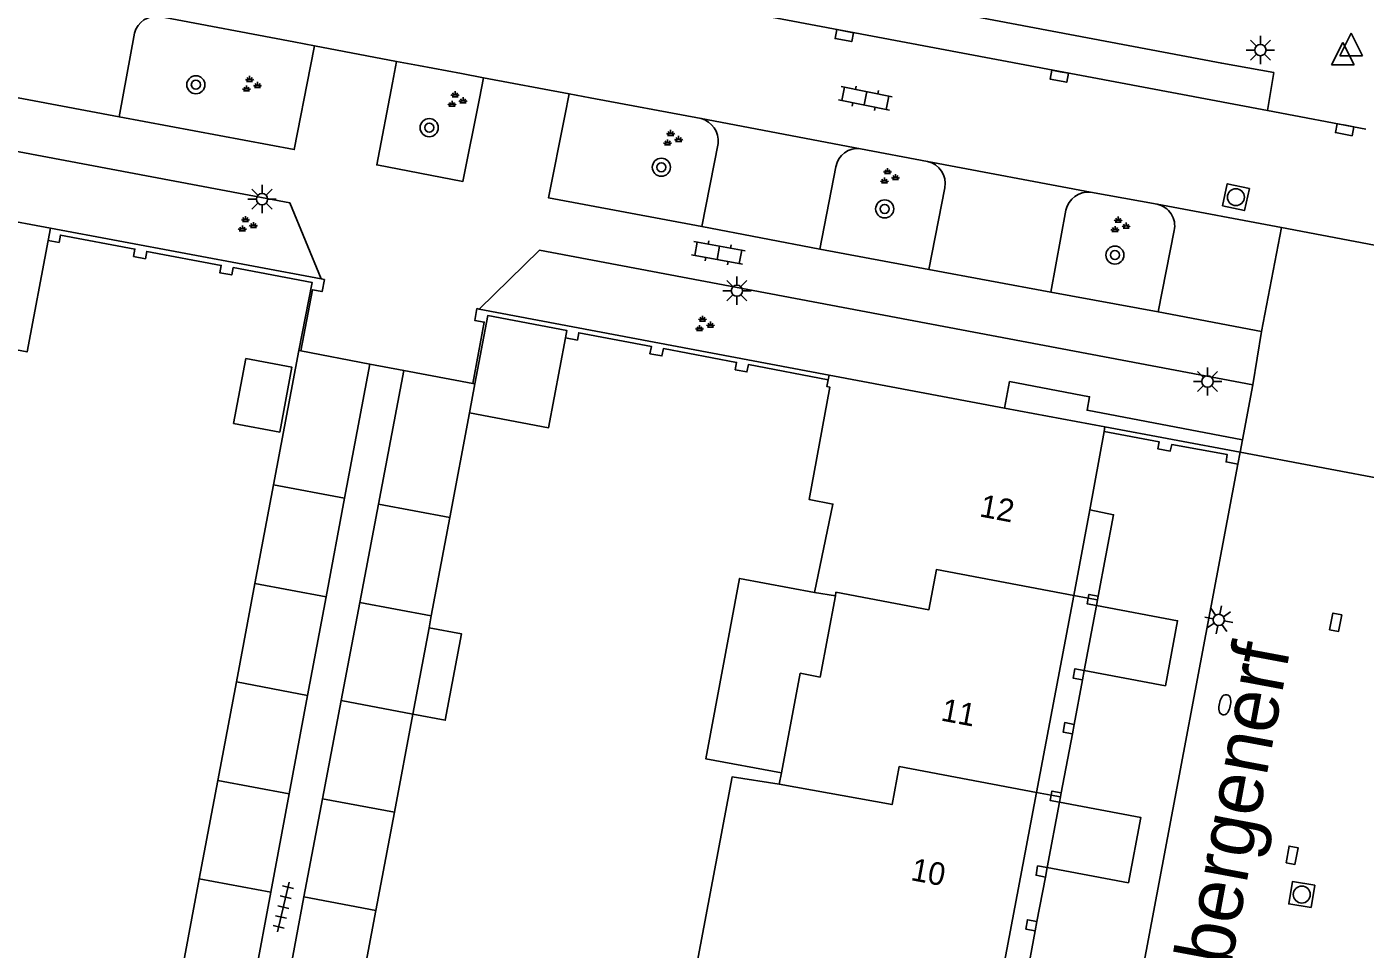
# Model space of a CAD drawing. Extents: x 124000 to 128010, y 398999 to 403000.
# Drawn here: x 126679.1 to 126738.3, y 399140 to 399180.7 of the extents above; entities that cross this region are included whole.
import ezdxf

# ---------------------------------------------------------------- set-up
doc = ezdxf.new("R2010")
doc.units = 0
for name, color, linetype in [('gg-afsc-muur', 7, 'Continuous'), ('gg-anno-huisnummerreeks BGT', 7, 'Continuous'), ('gg-anno-openbare ruimte label', 7, 'Continuous'), ('gg-bbg-bijgebouw', 7, 'Continuous'), ('gg-bbg-gedigitaliseerde bijgebouw', 7, 'Continuous'), ('gg-bbg-hoofdgebouw', 7, 'Continuous'), ('gg-bbg-luifel en loopbrug', 7, 'Continuous'), ('gg-bbg-onder overbouw', 7, 'Continuous'), ('gg-bbg-pand overbouw', 7, 'Continuous'), ('gg-bbg-pilaar onder overbouw', 7, 'Continuous'), ('gg-bbg-pilaar pand', 7, 'Continuous'), ('gg-bbg-tussenscheiding', 7, 'Continuous'), ('gg-bbg-tussenscheiding niveau 01', 7, 'Continuous'), ('gg-knt-verharding', 7, 'Continuous'), ('gg-knt-verharding nz', 7, 'Continuous'), ('gt-grn-groengrens', 7, 'Continuous'), ('gt-grn-weggrens', 7, 'Continuous'), ('gt-symb-boom', 7, 'Continuous'), ('gt-symb-brandkraan', 7, 'Continuous'), ('gt-symb-groenvak', 7, 'Continuous'), ('gt-symb-klinker verharding', 7, 'Continuous'), ('gt-symb-kolk', 7, 'Continuous'), ('gt-symb-kolk center center', 7, 'Continuous'), ('gt-symb-lichtmast', 7, 'Continuous'), ('gt-symb-rioolschacht', 7, 'Continuous'), ('gt-symb-tegel verharding', 7, 'Continuous'), ('gt-symb-waterafsluiter', 7, 'Continuous')]:
    doc.layers.add(name, color=color, linetype=linetype)

# ---------------------------------------------------------------- blocks, each defined once
blk = doc.blocks.new('gt0-LMAST')
at = {"layer": 'gt-symb-lichtmast'}
for p, q in [((-0.005, 0.246), (-0.005, 0.621)), ((-0.182, 0.173), (-0.447, 0.438)), ((0.172, 0.173), (0.437, 0.438)), ((-0.255, -0.004), (-0.63, -0.004)), ((-0.182, -0.181), (-0.447, -0.446)), ((-0.005, -0.254), (-0.005, -0.629)), ((0.437, -0.446), (0.172, -0.181)), ((0.245, -0.004), (0.62, -0.004))]:
    blk.add_line(p, q, dxfattribs=at)
blk.add_circle((-0.005, -0.004), 0.25, dxfattribs=at)
blk = doc.blocks.new('gt0-KOLK')
at = {"layer": 'gt-symb-kolk'}
blk.add_lwpolyline([(0, 0), (0.375, 0), (0.375, 0.4), (-0.375, 0.4), (-0.375, 0), (0, 0)], dxfattribs=at)
blk = doc.blocks.new('gt0-WAFSL')
at = {"layer": 'gt-symb-waterafsluiter'}
for p, q in [((-0.5, -0.333), (0, 0.667)), ((0, 0.667), (0.5, -0.333)), ((0.5, -0.333), (-0.5, -0.333))]:
    blk.add_line(p, q, dxfattribs=at)
blk = doc.blocks.new('gt0-BOOM')
at = {"layer": 'gt-symb-boom'}
for radius in [0.4, 0.2]:
    blk.add_circle((0, 0), radius, dxfattribs=at)
blk = doc.blocks.new('gt0-GRVAK')
at = {"layer": 'gt-symb-groenvak'}
for p, q in [((-0.11, 0.189), (-0.228, 0.24)), ((-0.182, 0.153), (0.088, 0.153)), ((-0.091, 0.211), (-0.156, 0.322)), ((-0.047, 0.214), (-0.047, 0.393)), ((-0.004, 0.211), (0.061, 0.322)), ((0.015, 0.189), (0.133, 0.24)), ((0.262, -0.052), (0.197, 0.059)), ((0.305, -0.049), (0.305, 0.13)), ((0.349, -0.052), (0.414, 0.059)), ((-0.245, -0.228), (-0.363, -0.177)), ((-0.318, -0.264), (-0.047, -0.264)), ((-0.226, -0.206), (-0.291, -0.095)), ((-0.183, -0.203), (-0.183, -0.024)), ((-0.139, -0.206), (-0.074, -0.095)), ((-0.12, -0.228), (-0.002, -0.177)), ((0.243, -0.074), (0.125, -0.023)), ((0.17, -0.11), (0.441, -0.11)), ((0.368, -0.074), (0.486, -0.023))]:
    blk.add_line(p, q, dxfattribs=at)
blk = doc.blocks.new('gt0-RS')
at = {"layer": 'gt-symb-rioolschacht'}
blk.add_lwpolyline([(-0.5, -0.5), (0.5, -0.5), (0.5, 0.5), (-0.5, 0.5)], close=True, dxfattribs=at)
blk.add_circle((0, 0), 0.375, dxfattribs=at)
blk = doc.blocks.new('gt0-KL1')
at = {"layer": 'gt-symb-klinker verharding'}
for p, q in [((-1.15, 0.3), (1.15, 0.3)), ((-1, -0.3), (-1, 0.3)), ((-0.5, 0.3), (-0.5, 0.45)), ((0, -0.3), (0, 0.3)), ((0.5, 0.3), (0.5, 0.45)), ((1, -0.3), (1, 0.3)), ((-1.15, -0.3), (1.15, -0.3)), ((-0.5, -0.45), (-0.5, -0.3)), ((0.5, -0.45), (0.5, -0.3))]:
    blk.add_line(p, q, dxfattribs=at)
blk = doc.blocks.new('gt0-BR')
at = {"layer": 'gt-symb-brandkraan'}
for centre, radius, start, end in [((-0.244, 0), 0.206, 107.56694, 252.43307), ((0.599, -2.664), 3, 106.89205, 107.56694), ((0, -0.691), 0.938, 73.10799, 106.89205), ((-0.599, -2.664), 3, 72.43309, 73.10799), ((0.244, 0), 0.206, 287.56695, 72.43309), ((0.599, 2.664), 3, 252.43307, 253.10797), ((0, 0.691), 0.938, 253.10797, 286.89206), ((-0.599, 2.664), 3, 286.89206, 287.56695)]:
    blk.add_arc(centre, radius, start, end, dxfattribs=at)
blk = doc.blocks.new('gt0-KOLKCC')
at = {"layer": 'gt-symb-kolk center center'}
blk.add_lwpolyline([(-0.375, 0.2), (0.375, 0.2), (0.375, -0.2), (-0.375, -0.2)], close=True, dxfattribs=at)
blk = doc.blocks.new('gt0-TEG1')
at = {"layer": 'gt-symb-tegel verharding'}
for p, q in [((-1.125, 0), (1.125, 0)), ((-0.9, -0.25), (-0.9, 0.25)), ((-0.45, -0.25), (-0.45, 0.25)), ((0, -0.25), (0, 0.25)), ((0.45, -0.25), (0.45, 0.25)), ((0.9, -0.25), (0.9, 0.25))]:
    blk.add_line(p, q, dxfattribs=at)

msp = doc.modelspace()

# ---------------------------------------------------------------- linework, layer by layer
at = {"layer": 'gg-afsc-muur'}
for p, q in [((126692.156, 399169.58), (126680.192, 399171.824)), ((126714.593, 399165.336), (126699.127, 399168.252)), ((126726.765, 399163.043), (126732.739, 399161.925)), ((126732.641, 399161.4), (126732.739, 399161.925))]:
    msp.add_line(p, q, dxfattribs=at)
for points in [[(126680.09, 399171.284), (126680.571, 399171.194), (126680.632, 399171.518), (126683.924, 399170.898), (126683.863, 399170.574), (126684.384, 399170.476), (126684.445, 399170.8), (126687.734, 399170.181), (126687.673, 399169.856), (126688.204, 399169.756), (126688.265, 399170.081), (126691.747, 399169.425), (126691.165, 399166.421)], [(126691.25, 399166.405), (126691.77, 399169.105), (126692.193, 399169.024), (126692.295, 399169.554), (126692.156, 399169.58)], [(126699.127, 399168.252), (126699.029, 399168.27), (126698.932, 399167.752), (126699.354, 399167.673), (126698.846, 399164.97)], [(126714.55, 399165.131), (126711.018, 399165.796), (126710.957, 399165.472), (126710.437, 399165.57), (126710.498, 399165.894), (126707.265, 399166.504), (126707.203, 399166.179), (126706.673, 399166.279), (126706.734, 399166.604), (126703.53, 399167.208), (126703.469, 399166.883), (126702.939, 399166.983)], [(126726.729, 399162.844), (126729.16, 399162.387), (126729.102, 399162.08), (126729.65, 399161.975), (126729.717, 399162.267), (126732.169, 399161.822), (126732.12, 399161.5), (126732.641, 399161.4)]]:
    msp.add_lwpolyline(points, dxfattribs=at)
at = {"layer": 'gg-bbg-bijgebouw'}
for p, q in [((126690.046, 399160.488), (126691.165, 399166.421)), ((126691.165, 399166.421), (126691.25, 399166.405)), ((126691.25, 399166.405), (126694.294, 399165.818)), ((126694.294, 399165.818), (126693.183, 399159.897)), ((126694.677, 399159.632), (126695.795, 399165.539)), ((126695.795, 399165.539), (126698.846, 399164.97)), ((126698.846, 399164.97), (126698.944, 399164.952)), ((126698.703, 399163.669), (126697.831, 399159.038)), ((126688.405, 399151.779), (126689.226, 399156.134)), ((126692.367, 399155.542), (126691.551, 399151.186)), ((126693.034, 399150.955), (126693.856, 399155.294)), ((126697.014, 399154.695), (126696.915, 399154.17)), ((126696.915, 399154.17), (126696.198, 399150.359)), ((126686.766, 399143.085), (126687.586, 399147.432)), ((126690.736, 399146.839), (126689.921, 399142.491)), ((126691.391, 399142.283), (126692.213, 399146.619)), ((126695.382, 399146.023), (126694.566, 399141.686))]:
    msp.add_line(p, q, dxfattribs=at)
at = {"layer": 'gg-bbg-gedigitaliseerde bijgebouw'}
for p, q in [((126693.183, 399159.897), (126690.046, 399160.488)), ((126697.831, 399159.038), (126694.677, 399159.632)), ((126689.226, 399156.134), (126692.367, 399155.542)), ((126693.856, 399155.294), (126697.014, 399154.695)), ((126691.551, 399151.186), (126688.405, 399151.779)), ((126696.198, 399150.359), (126693.034, 399150.955)), ((126687.586, 399147.432), (126690.736, 399146.839)), ((126692.213, 399146.619), (126695.382, 399146.023)), ((126689.921, 399142.491), (126686.766, 399143.085)), ((126694.566, 399141.686), (126691.391, 399142.283))]:
    msp.add_line(p, q, dxfattribs=at)
for points in [[(126702.939, 399166.983), (126703, 399167.308), (126699.511, 399167.965), (126698.944, 399164.952)], [(126702.939, 399166.983), (126702.192, 399163.012), (126698.703, 399163.669)], [(126688.818, 399166.063), (126688.279, 399163.198), (126690.318, 399162.814), (126690.857, 399165.679), (126688.818, 399166.063)]]:
    msp.add_lwpolyline(points, dxfattribs=at)
at = {"layer": 'gg-bbg-hoofdgebouw'}
for p, q in [((126676.821, 399172.456), (126680.192, 399171.824)), ((126680.192, 399171.824), (126680.09, 399171.284)), ((126714.593, 399165.336), (126714.55, 399165.131)), ((126722.326, 399163.879), (126714.593, 399165.336)), ((126726.765, 399163.043), (126722.326, 399163.879)), ((126726.729, 399162.844), (126726.106, 399159.388)), ((126726.765, 399163.043), (126726.729, 399162.844)), ((126713.947, 399155.727), (126714.866, 399155.583)), ((126712.479, 399147.761), (126712.386, 399147.269))]:
    msp.add_line(p, q, dxfattribs=at)
for points in [[(126680.09, 399171.284), (126679.163, 399166.358), (126674.593, 399167.218)], [(126714.55, 399165.131), (126714.485, 399164.824), (126714.622, 399164.795), (126713.697, 399159.842), (126714.751, 399159.638), (126713.947, 399155.727)], [(126714.866, 399155.583), (126714.183, 399151.996), (126713.311, 399152.164), (126712.479, 399147.761)], [(126712.386, 399147.269), (126710.3, 399147.585), (126708.712, 399139.147)]]:
    msp.add_lwpolyline(points, dxfattribs=at)
at = {"layer": 'gg-bbg-luifel en loopbrug'}
for p, q in [((126689.226, 399156.134), (126690.046, 399160.488)), ((126693.183, 399159.897), (126692.367, 399155.542)), ((126693.856, 399155.294), (126694.677, 399159.632)), ((126697.831, 399159.038), (126697.014, 399154.695)), ((126687.586, 399147.432), (126688.405, 399151.779)), ((126691.551, 399151.186), (126690.736, 399146.839)), ((126692.213, 399146.619), (126693.034, 399150.955)), ((126696.198, 399150.359), (126695.382, 399146.023)), ((126685.947, 399138.742), (126686.766, 399143.085)), ((126689.921, 399142.491), (126689.107, 399138.148)), ((126690.568, 399137.935), (126691.391, 399142.283)), ((126694.566, 399141.686), (126693.748, 399137.337))]:
    msp.add_line(p, q, dxfattribs=at)
for points in [[(126713.947, 399155.727), (126710.634, 399156.35), (126709.136, 399148.39), (126712.479, 399147.761)], [(126726.396, 399155.152), (126729.974, 399154.484), (126729.439, 399151.616), (126725.856, 399152.285)], [(126696.198, 399150.359), (126697.632, 399150.089), (126698.349, 399153.9), (126696.915, 399154.17)], [(126724.759, 399146.465), (126728.347, 399145.795), (126727.808, 399142.908), (126724.215, 399143.579)]]:
    msp.add_lwpolyline(points, dxfattribs=at)
at = {"layer": 'gg-bbg-onder overbouw'}
for p, q in [((126725.391, 399155.605), (126726.106, 399159.388)), ((126723.744, 399146.899), (126725.391, 399155.605)), ((126722.085, 399138.125), (126723.744, 399146.899))]:
    msp.add_line(p, q, dxfattribs=at)
at = {"layer": 'gg-bbg-pand overbouw'}
for p, q in [((126725.856, 399152.285), (126726.396, 399155.152)), ((126725.778, 399151.869), (126725.408, 399149.907)), ((126725.329, 399149.491), (126724.837, 399146.88)), ((126724.215, 399143.579), (126724.759, 399146.465)), ((126724.137, 399143.163), (126723.767, 399141.2)), ((126723.688, 399140.784), (126723.194, 399138.163))]:
    msp.add_line(p, q, dxfattribs=at)
msp.add_lwpolyline([(126726.472, 399155.568), (126727.152, 399159.162), (126726.106, 399159.388)], dxfattribs=at)
at = {"layer": 'gg-bbg-pilaar onder overbouw'}
for points in [[(126726.472, 399155.568), (126726.059, 399155.646), (126726.031, 399155.485)], [(126726.031, 399155.485), (126725.987, 399155.229), (126726.396, 399155.152)], [(126725.856, 399152.285), (126725.442, 399152.363), (126725.37, 399151.946), (126725.778, 399151.869)], [(126725.408, 399149.907), (126724.995, 399149.985), (126724.923, 399149.568), (126725.329, 399149.491)], [(126724.395, 399146.776), (126724.354, 399146.541), (126724.759, 399146.465)], [(126724.837, 399146.88), (126724.426, 399146.958), (126724.395, 399146.776)], [(126724.215, 399143.579), (126723.796, 399143.658), (126723.724, 399143.241), (126724.137, 399143.163)], [(126723.767, 399141.2), (126723.347, 399141.279), (126723.275, 399140.862), (126723.688, 399140.784)]]:
    msp.add_lwpolyline(points, dxfattribs=at)
at = {"layer": 'gg-bbg-pilaar pand'}
for p, q in [((126726.472, 399155.568), (126726.443, 399155.407)), ((126726.443, 399155.407), (126726.396, 399155.152)), ((126725.778, 399151.869), (126725.856, 399152.285)), ((126725.329, 399149.491), (126725.408, 399149.907)), ((126724.759, 399146.465), (126724.803, 399146.7)), ((126724.803, 399146.7), (126724.837, 399146.88)), ((126724.137, 399143.163), (126724.215, 399143.579)), ((126723.688, 399140.784), (126723.767, 399141.2))]:
    msp.add_line(p, q, dxfattribs=at)
at = {"layer": 'gg-bbg-tussenscheiding'}
msp.add_line((126698.944, 399164.952), (126698.703, 399163.669), dxfattribs=at)
for points in [[(126714.866, 399155.583), (126714.889, 399155.745), (126718.992, 399154.972), (126719.327, 399156.744), (126725.391, 399155.605)], [(126712.386, 399147.269), (126717.365, 399146.367), (126717.68, 399148.039), (126723.744, 399146.899)]]:
    msp.add_lwpolyline(points, dxfattribs=at)
at = {"layer": 'gg-bbg-tussenscheiding niveau 01'}
for p, q in [((126725.391, 399155.605), (126726.031, 399155.485)), ((126726.031, 399155.485), (126726.443, 399155.407)), ((126723.744, 399146.899), (126724.395, 399146.776)), ((126724.395, 399146.776), (126724.803, 399146.7))]:
    msp.add_line(p, q, dxfattribs=at)
at = {"layer": 'gg-knt-verharding'}
for p, q in [((126685.013, 399181.168), (126690.945, 399180.054)), ((126683.229, 399176.739), (126683.909, 399180.44)), ((126691.857, 399179.883), (126690.945, 399180.054)), ((126691.681, 399178.98), (126691.857, 399179.883)), ((126695.474, 399179.19), (126695.294, 399178.237)), ((126696.455, 399179.006), (126695.474, 399179.19)), ((126698.345, 399178.651), (126696.455, 399179.006)), ((126698.345, 399178.651), (126699.324, 399178.467)), ((126699.324, 399178.467), (126699.142, 399177.557)), ((126703.101, 399177.757), (126702.908, 399176.79)), ((126704.033, 399177.583), (126703.101, 399177.757)), ((126704.033, 399177.583), (126708.928, 399176.668)), ((126738.295, 399176.192), (126733.941, 399177.017)), ((126709.678, 399175.565), (126708.969, 399171.891)), ((126715.973, 399175.329), (126718.929, 399174.768)), ((126714.179, 399170.898), (126714.887, 399174.537)), ((126719.69, 399173.61), (126718.991, 399169.991)), ((126725.039, 399172.618), (126724.381, 399168.991)), ((126729.829, 399171.714), (126729.112, 399168.123)), ((126718.991, 399169.991), (126714.179, 399170.898)), ((126724.381, 399168.991), (126729.112, 399168.123)), ((126694.294, 399165.818), (126695.795, 399165.539)), ((126732.843, 399162.477), (126733.302, 399164.904)), ((126732.739, 399161.925), (126732.843, 399162.477)), ((126732.641, 399161.4), (126723.192, 399111.208))]:
    msp.add_line(p, q, dxfattribs=at)
for points in [[(126659.132, 399191.107), (126659.548, 399192.782), (126731.931, 399179.108), (126734.226, 399178.697), (126733.941, 399177.017)], [(126691.681, 399178.98), (126690.964, 399175.296), (126683.229, 399176.739)], [(126662.783, 399178.218), (126690.772, 399172.937), (126692.156, 399169.58)], [(126699.142, 399177.557), (126698.409, 399173.891), (126694.608, 399174.614), (126695.294, 399178.237)], [(126708.969, 399171.891), (126702.184, 399173.166), (126702.908, 399176.79)], [(126733.302, 399164.904), (126701.789, 399170.847), (126699.127, 399168.252)]]:
    msp.add_lwpolyline(points, dxfattribs=at)
for centre, radius, start, end in [((126684.85, 399180.215), 0.967, 80.28048, 166.52286), ((126708.665, 399175.683), 1.02, 353.38353, 75.04503), ((126715.832, 399174.382), 0.957, 81.50264, 170.70254), ((126718.73, 399173.808), 0.98, 348.31608, 78.30715), ((126726.053, 399172.378), 1.042, 85.63844, 166.69633), ((126728.873, 399171.92), 0.978, 347.83559, 78.37809)]:
    msp.add_arc(centre, radius, start, end, dxfattribs=at)
at = {"layer": 'gg-knt-verharding nz'}
for p, q in [((126679.614, 399187.27), (126733.941, 399177.017)), ((126691.857, 399179.883), (126695.474, 399179.19)), ((126699.324, 399178.467), (126703.101, 399177.757)), ((126677.989, 399177.73), (126683.229, 399176.739)), ((126715.973, 399175.329), (126708.928, 399176.668)), ((126726.132, 399173.417), (126718.929, 399174.768)), ((126726.132, 399173.417), (126729.07, 399172.878)), ((126734.56, 399171.853), (126729.07, 399172.878)), ((126708.969, 399171.891), (126714.179, 399170.898)), ((126733.676, 399167.262), (126734.56, 399171.853)), ((126734.56, 399171.853), (126745.463, 399169.769)), ((126718.991, 399169.991), (126724.381, 399168.991)), ((126729.112, 399168.123), (126733.676, 399167.262))]:
    msp.add_line(p, q, dxfattribs=at)
at = {"layer": 'gt-grn-groengrens'}
msp.add_lwpolyline([(126732.843, 399162.477), (126725.977, 399163.785), (126726.093, 399164.374), (126722.557, 399165.048), (126722.326, 399163.879)], dxfattribs=at)
at = {"layer": 'gt-grn-weggrens'}
for p, q in [((126733.676, 399167.262), (126733.302, 399164.904)), ((126732.739, 399161.925), (126743.628, 399159.879))]:
    msp.add_line(p, q, dxfattribs=at)

# ---------------------------------------------------------------- block references
at = {"layer": 'gt-symb-boom'}
for p in [(126686.615, 399178.158), (126696.922, 399176.263), (126707.176, 399174.515), (126717.041, 399172.675), (126727.207, 399170.635)]:
    msp.add_blockref('gt0-BOOM', p, dxfattribs=at)
at = {"layer": 'gt-symb-brandkraan', "rotation": -101.65840162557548}
msp.add_blockref('gt0-BR', (126732.063, 399150.774), dxfattribs=at)
at = {"layer": 'gt-symb-groenvak'}
for p in [(126689.036, 399178.152), (126698.112, 399177.475), (126707.633, 399175.769), (126717.211, 399174.084), (126688.852, 399171.966), (126727.398, 399171.941), (126709.042, 399167.565)]:
    msp.add_blockref('gt0-GRVAK', p, dxfattribs=at)
at = {"layer": 'gt-symb-klinker verharding'}
for p, rotation in [((126716.188, 399177.56), 168.81367070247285), ((126709.688, 399170.736), 169.5773454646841)]:
    msp.add_blockref('gt0-KL1', p, dxfattribs=dict(at, rotation=rotation))
at = {"layer": 'gt-symb-kolk'}
for p, rotation in [((126715.291, 399180.525), 169.34163849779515), ((126724.786, 399178.734), 169.34163849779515), ((126737.394, 399176.368), 169.2183832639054)]:
    msp.add_blockref('gt0-KOLK', p, dxfattribs=dict(at, rotation=rotation))
at = {"layer": 'gt-symb-kolk center center'}
for p, rotation in [((126736.96, 399154.417), -100.89418298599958), ((126735.033, 399144.123), 79.45426563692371)]:
    msp.add_blockref('gt0-KOLKCC', p, dxfattribs=dict(at, rotation=rotation))
at = {"layer": 'gt-symb-lichtmast'}
for p in [(126733.64, 399179.693), (126689.542, 399173.11), (126710.521, 399169.067), (126731.304, 399165.055)]:
    msp.add_blockref('gt0-LMAST', p, dxfattribs=at)
at = {"layer": 'gt-symb-lichtmast', "rotation": -100.78161673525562}
msp.add_blockref('gt0-LMAST', (126731.799, 399154.516), dxfattribs=at)
at = {"layer": 'gt-symb-rioolschacht'}
for p, rotation in [((126732.551, 399173.193), -12.410774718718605), ((126735.462, 399142.389), 80.622420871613)]:
    msp.add_blockref('gt0-RS', p, dxfattribs=dict(at, rotation=rotation))
at = {"layer": 'gt-symb-tegel verharding', "rotation": 76.82507339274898}
msp.add_blockref('gt0-TEG1', (126690.48, 399141.837), dxfattribs=at)
at = {"layer": 'gt-symb-waterafsluiter'}
for p in [(126737.649, 399179.773), (126737.281, 399179.364)]:
    msp.add_blockref('gt0-WAFSL', p, dxfattribs=at)

# ---------------------------------------------------------------- texts
at = {"layer": 'gg-anno-huisnummerreeks BGT'}
for s, p in [('12', (126721.19, 399159.097)), ('11', (126719.485, 399150.082)), ('10', (126718.151, 399143.033))]:
    msp.add_text(s, height=1, rotation=349.3, dxfattribs=at).set_placement(p)
at = {"layer": 'gg-anno-openbare ruimte label'}
msp.add_text('Steenbergenerf', height=2.5, rotation=79.4, dxfattribs=at).set_placement((126730.72, 399130.578))

doc.saveas('drawing.dxf')
